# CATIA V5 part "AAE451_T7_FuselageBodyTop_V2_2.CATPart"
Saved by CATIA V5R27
Part number: FT2
Bounding box of the stored display mesh (mm): x -98.453 to 98.453, y -60 to 200, z -0.002 to 60
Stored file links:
  W:\AAE 451\AAE451_T7_FuselageBodyTop_V2_2.CATPart
  W:\AAE 451\AAE451_T7_FuselageBody.CATPart
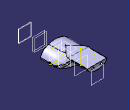
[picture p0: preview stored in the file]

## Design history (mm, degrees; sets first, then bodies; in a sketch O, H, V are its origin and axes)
Body1 (main body)
Body2
  Plane1: type Offset, RefPlane zx-plane, Offset 250, reversed
  Plane2: type Offset, RefPlane zx-plane, Offset 100
  Sketch1 on Plane1, origin (0, -250, 0), H (-1, 0, 0), V (0, 0, 1)
    circle A1 centre (0, 0) radius 24.5
    distance O A1 = 24.5
  Plane3: type Offset, RefPlane zx-plane, Offset 150, reversed
  Sketch2 on Plane2, origin (0, 100, 0), H (-1, 0, 0), V (0, 0, 1)
    construction line L1 (0, 60) -> (0, -40)
    point P1 (0, 60)
    construction line L2 (-92.2886, 30) -> (87.7114, 30)
    point P5 (0, 30)
    coincidence: P1 V, P5 L2, P5 L1
    vertical: L1 V
    horizontal: L2 H
  Sketch3 on Plane2, origin (0, 100, 0), H (-1, 0, 0), V (0, 0, 1)
    construction line L1 (0, -100) -> (0, 70)
    point P1 (0, -100)
    construction line L2 (-103.4986, 30) -> (116.5014, 30)
    point P5 (0, 30)
    point P6 (0, 60)
    construction line L3 (-60, 60) -> (60, 60)
    point P7 (-60, 60)
    reference projected curve E1 from Sketch4.E1
    ellipse A1 centre (0, 60) semi-axes 60, 35 rotation 180 from (-60, 60) to (60, 60)
    point P8 (-60, 60)
    point P9 (60, 60)
    point P10 (60, 60)
    point P11 (-60, 60)
    ellipse A2 centre (0, 60) semi-axes 60, 35 rotation 180 from (-60, 60) to (60, 60)
    "Radius" A1 = 60
    "Radius" A1 = 35
    coincidence: P1 V, P5 L2, P5 L1, P6 L1, A1 P7, P7 L3, P6 L3
    vertical: L1 V
    horizontal: L2 H, L3 H, A1 H
    tangency: L3 E1
    symmetry: P9 P10 L3, P8 P11 L3, A1 A2 L3
  Sketch4 on zx-plane, origin (0, 0, 0), H (-1, 0, 0), V (0, 0, 1)
    projected curve E1 from Sketch5.A1
  Sketch5 on Plane3, origin (0, -150, 0), H (-1, 0, 0), V (0, 0, 1)
    construction line L1 (50, 50) -> (50, -50)
    construction line L2 (50, -50) -> (-50, -50)
    construction line L3 (-50, -50) -> (-50, 50)
    construction line L4 (-50, 50) -> (50, 50)
    point P1 (50, 50)
    point P2 (50, -50)
    point P3 (-50, -50)
    point P4 (-50, 50)
    construction line L5 (0, -60) -> (0, 90)
    point P5 (0, -60)
    construction line L6 (-100, 0) -> (110, 0)
    point P7 (-100, 0)
    ellipse A1 centre (0, 0) semi-axes 90.4534, 60 rotation 0
    point P9 (0, 60)
    length L1 = 100
    length L4 = 100
    vertical: L1 V, L3 V, L5 V
    horizontal: L2 H, L4 H, L6 H, A1 H
    equidistance: L1 L3 O, L2 L4 O
    coincidence: P5 V, P7 H, P9 L5, A1 P9, P2 A1, A1 P3, P1 A1, P4 A1
    parallelism: A1 L6
  Loft1: solid, Sections (Sketch3; Sketch4; Sketch5; Sketch1)
  Sketch6 on face of Loft1, origin (0, 100, 0), H (-1, 0, 0), V (0, 0, 1)
    line L1 (-70, 95) -> (70, 95)
    line L2 (70, 95) -> (70, 60)
    line L3 (70, 60) -> (-70, 60)
    line L4 (-70, 60) -> (-70, 95)
    reference projected curve E1 from edge [face of Loft1 | face of Loft1]
    construction line L5 (-60, 60) -> (60, 60)
    length L1 = 140
    horizontal: L1 H, L3 H, L5 H
    vertical: L2 V, L4 V
    coincidence: L3 L5
    tangency: L1 E1
    symmetry: L4 L2 V
  Pocket1: profile Sketch6, direction (0, -1, 0), through (limit type 6)
  Plane4: type Offset, RefPlane Plane2, Offset 100
  Sketch7 on Plane4, origin (0, 200, 0), H (-1, 0, 0), V (0, 0, 1)
    projected line E2 (-60, 60) -> (60, 60) from edge [face of Loft1 | face of Pocket1 from Sketch6.L3]
  Pad1: profile Sketch7, direction (0, 1, 0), up to the existing solid (limit type 3)
  Sketch8 on face of Loft1, origin (0, -250, 0), H (1, 0, 0), V (0, 0, 1)
    line L1 (-100, 0) -> (100, 0)
    point P1 (-100, 0)
    point P2 (100, 0)
    line L2 (-64.2043, -62) -> (64.2043, -62)
    point P3 (-64.2043, -62)
    point P4 (64.2043, -62)
    line L3 (100, 0) -> (64.2043, -62)
    line L4 (-100, 0) -> (-64.2043, -62)
    angle L4 L1 = 60
    distance L1 L2 = 62
    length L1 = 200
    horizontal: L1 H, L2 H
    symmetry: P2 P1 V, P3 P4 V
    coincidence: L1 H
  Pocket2: profile Sketch8, direction (0, 1, 0), through (limit type 6)
  Sketch9 on face of Pocket2 from Sketch8.L1, origin (0, 0, 0), H (1, 0, 0), V (0, -1, 0)
  Sketch10 on start face of Pad1, origin (0, 200, 0), H (-1, 0, 0), V (0, 0, 1)
    circle A1 centre (26, 46.5) radius 6.85
    point P1 (26, 46.5)
    circle A2 centre (-26, 46.5) radius 6.85
    reference projected line E1 (60, 60) -> (-60, 60) from edge [face of Pad1 | start face of Pad1]
    radius A1 = 6.85
    distance V P1 = 26
    distance E1 P1 = 13.5
    symmetry: A2 A1 V
  Pocket3: profile Sketch10, direction (0, -1, 0), length 300
  Plane5 "MOTOR": type Offset, RefPlane Plane1, Offset 4
  Plane6 "BATTERY": type Offset, RefPlane Plane1, Offset 88.5
  Shell1: ExtOffset 0, Face face of Pocket2 from Sketch8.L1, IntOffset 2
  Plane7: type Offset, RefPlane xy-plane, Offset 40
  Sketch11 on Plane7, origin (0, 0, 40), H (1, 0, 0), V (0, 1, 0)
    line L1 (69.2382, 78.9472) -> (-67.3756, 82.6205)
  Pad2: profile Sketch11, direction (0, 0, 1), up to the existing solid (limit type 2)
  Sketch12 on face of Pocket2 from Sketch8.L1, origin (0, 0, 0), H (1, 0, 0), V (0, -1, 0)
    arc A1 centre (-93.4534, 150) radius 5 from (-93.4534, 155) to (-93.4534, 145) ccw
    point P1 (-93.4534, 150)
    line L1 (-93.4534, 145) -> (-88.4534, 145)
    line L2 (-88.4534, 145) -> (-88.4534, 155)
    line L3 (-88.4534, 155) -> (-93.4534, 155)
    reference projected curve E1 from edge [face of Shell1 | face of Pocket2 from Sketch8.L1]
    reference intersected line E2 through (0, 150) direction (1, 0) from Plane3
    distance P1 L2 = 5
    distance L3 L1 = 10
    horizontal: L1 H, L3 H
    tangency: L2 E1, L1 A1, L3 A1
    coincidence: E2 P1
    vertical: L2 V
  Pad3: profile Sketch12, direction (0, 0, 1), length 10
  Sketch13 on face of Pad3, origin (0, 0, 0), H (1, 0, 0), V (0, -1, 0)
    circle A1 centre (-93.4534, 150) radius 2.5
    reference projected arc E1 centre (-93.4534, 150) radius 5 from (-93.4534, 155) to (-93.4534, 145) ccw from edge [face of Pad3 from Sketch12.A1 | start face of Pad3]
    radius A1 = 2.5
    concentricity: A1 E1
  Pocket4: profile Sketch13, direction (0, 0, 1), through (limit type 6)
  RectPattern1: of Pad3, direction 1 instances 3, spacing 75, along yz-plane
  RectPattern2: of Pocket4, direction 1 instances 3, spacing 75, along yz-plane
  Mirror1: of RectPattern1, about yz-plane
  Mirror2: of RectPattern2, about yz-plane
  Plane8 "PRINT CAPACITY": type Offset, RefPlane Plane4, Offset 260, reversed
  Sketch14 on Plane8, origin (0, -60, 0), H (-1, 0, 0), V (0, 0, 1)
    point P1 (0.1956, 30)
    line L1 (121.21, 60) -> (121.21, 0)
    line L2 (121.21, 0) -> (-120.8188, 0)
    line L3 (-120.8188, 0) -> (-120.8188, 60)
    line L4 (-120.8188, 60) -> (121.21, 60)
    reference projected line E1 (-63.056, 60) -> (62.8781, 60) from edge [face of Pad1 | face of Loft1]
    vertical: L1 V, L3 V
    horizontal: L2 H, L4 H
    equidistance: L1 L3 P1, L2 L4 P1
    coincidence: L4 E1, L2 H
  Pocket5: profile Sketch14, direction (0, -1, 0), through (limit type 6)
  Sketch15 on start face of Pad1, origin (0, 200, 0), H (-1, 0, 0), V (0, 0, 1)
    projected circle E1 centre (26, 46.5) radius 6.85 from edge [start face of Pad1 | face of Pocket3 from Sketch10.A1]
    projected circle E2 centre (-26, 46.5) radius 6.85 from edge [start face of Pad1 | face of Pocket3 from Sketch10.A2]
  Pocket6: profile Sketch15, direction (0, -1, 0), through (limit type 3)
